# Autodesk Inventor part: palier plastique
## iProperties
Created: 2002-05
Part Number: palier plastique
Material: Par défaut
Document SubType Name: Modélisation
Designer: REVEST Pierre
Control State: 0
Master: False
Checked Out: False
Shininess: 69.0
Length Units: 11269
Angle Units: 11279
Time Units: 11290
Mass Units: 11283
Length Display Precision: 3
Angle Display Precision: 2
Density: 0.0
Volumn: 0.0
Area: 0.0
PropertySet Name: Model Information
Author: REVEST Pierre
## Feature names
1. Extrusion1
2. Extrusion2
3. Extrusion4
4. Congé1 [Fillet]
5. Extrusion5
6. Extrusion6
7. Congé2 [Fillet]
8. Congé3 [Fillet]
9. Congé4 [Fillet]
10. Perçage1 [Hole]
